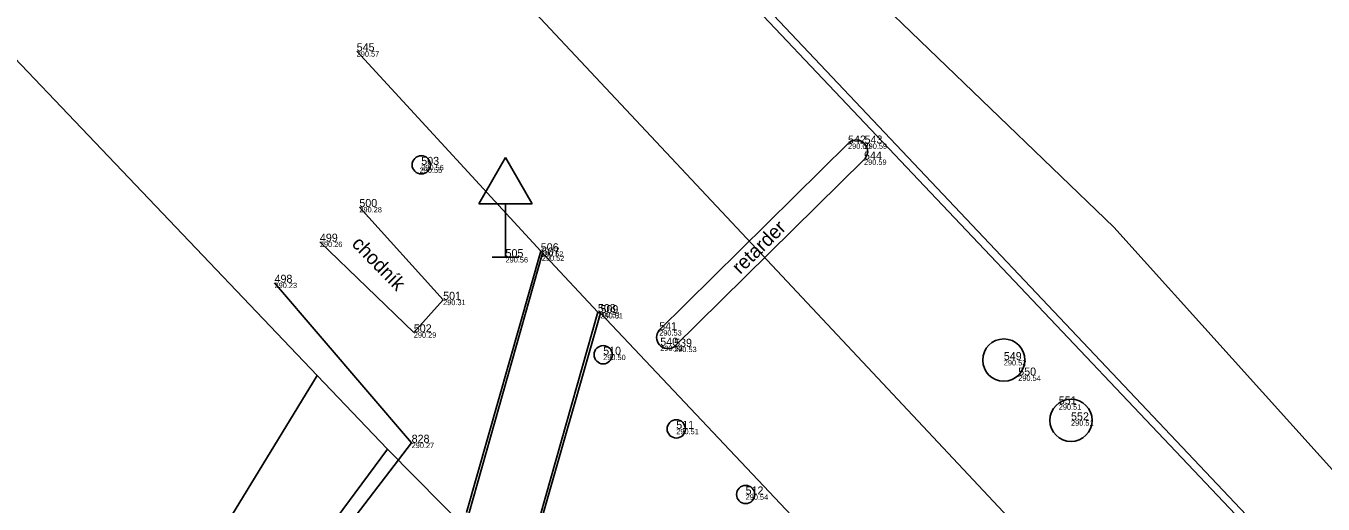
# Model space of a CAD drawing. Extents: x -805057 to -804930, y -994399 to -994240.
# Drawn here: x -805024.17 to -804999.86, y -994267.14 to -994258.18 of the extents above; entities that cross this region are included whole.
import ezdxf

# ---------------------------------------------------------------- set-up
doc = ezdxf.new("R2010")
doc.units = 0
for name, color, linetype in [('bod cislo', 7, 'Continuous'), ('bod pozice', 7, 'Continuous'), ('bod výška', 7, 'Continuous'), ('kanalizace', 7, 'Continuous'), ('Katastralni mapa', 7, 'Continuous'), ('komunikace', 7, 'Continuous'), ('plot', 7, 'Continuous'), ('popis', 7, 'Continuous'), ('sloupek', 7, 'Continuous'), ('značka', 7, 'Continuous')]:
    doc.layers.add(name, color=color, linetype=linetype)

msp = doc.modelspace()

# ---------------------------------------------------------------- linework, layer by layer
at = {"layer": 'bod pozice'}
for p, q in [((-805017.97, -994258.65), (-805017.97, -994258.65)), ((-805008.76, -994260.38), (-805008.76, -994260.38)), ((-805008.45, -994260.38), (-805008.45, -994260.38)), ((-805016.76, -994260.78), (-805016.76, -994260.78)), ((-805008.46, -994260.68), (-805008.46, -994260.68)), ((-805017.92, -994261.57), (-805017.92, -994261.57)), ((-805018.66, -994262.22), (-805018.66, -994262.22)), ((-805015.18, -994262.51), (-805015.18, -994262.51)), ((-805014.52, -994262.4), (-805014.52, -994262.4)), ((-805014.5, -994262.48), (-805014.5, -994262.48)), ((-805019.51, -994262.99), (-805019.51, -994262.99)), ((-805016.35, -994263.31), (-805016.35, -994263.31)), ((-805013.45, -994263.54), (-805013.45, -994263.54)), ((-805013.4, -994263.56), (-805013.4, -994263.56)), ((-805016.9, -994263.92), (-805016.9, -994263.92)), ((-805012.3, -994263.88), (-805012.3, -994263.88)), ((-805012.28, -994264.17), (-805012.28, -994264.17)), ((-805012.02, -994264.19), (-805012.02, -994264.19)), ((-805013.35, -994264.34), (-805013.35, -994264.34)), ((-805005.84, -994264.44), (-805005.84, -994264.44)), ((-805005.57, -994264.73), (-805005.57, -994264.73)), ((-805004.81, -994265.27), (-805004.81, -994265.27)), ((-805011.98, -994265.73), (-805011.98, -994265.73)), ((-805004.58, -994265.57), (-805004.58, -994265.57)), ((-805016.94, -994265.99), (-805016.94, -994265.99)), ((-805010.68, -994266.96), (-805010.68, -994266.96))]:
    msp.add_line(p, q, dxfattribs=at)
at = {"layer": 'kanalizace'}
for centre in [(-805005.84, -994264.44), (-805004.58, -994265.57)]:
    msp.add_circle(centre, 0.396, dxfattribs=at)
at = {"layer": 'Katastralni mapa'}
for points in [[(-805025.53, -994257.57), (-805018.71, -994264.73)], [(-805008.4, -994257.49), (-805003.78, -994261.95)], [(-805003.78, -994261.95), (-804999.34, -994266.87)], [(-805018.71, -994264.73), (-805029.78, -994282.86)], [(-805018.71, -994264.73), (-805017.39, -994266.11)], [(-805017.39, -994266.11), (-805024.09, -994275.16)], [(-805017.39, -994266.11), (-804988.46, -994295.41)]]:
    msp.add_lwpolyline(points, dxfattribs=at)
at = {"layer": 'komunikace'}
for p, q in [((-805014.33, -994253.78), (-804993.36, -994275.93)), ((-804993.27, -994275.83), (-805014.23, -994253.66)), ((-805005.75, -994267.39), (-805015.94, -994256.52)), ((-805017.97, -994258.65), (-805014.52, -994262.4)), ((-805008.76, -994260.38), (-805012.3, -994263.88)), ((-805012.02, -994264.19), (-805008.46, -994260.68)), ((-805017.92, -994261.57), (-805016.35, -994263.31)), ((-805016.9, -994263.92), (-805018.66, -994262.22)), ((-805015.91, -994267.3), (-805014.52, -994262.4)), ((-805014.487, -994262.435), (-805015.87, -994267.32)), ((-805013.45, -994263.54), (-805014.52, -994262.4)), ((-805016.35, -994263.31), (-805016.9, -994263.92)), ((-805014.79, -994268.27), (-805013.45, -994263.54)), ((-805013.45, -994263.54), (-805013.4, -994263.56)), ((-805013.4, -994263.56), (-805014.75, -994268.28)), ((-805009.04, -994268.18), (-805013.4, -994263.56))]:
    msp.add_line(p, q, dxfattribs=at)
for centre, major_axis, ratio, start_param, end_param in [((-805008.605, -994260.525), (-0.007, -0.212), 0.99948, 0.785675, 3.993875), ((-805012.138, -994264.015), (0.141, -0.157), 0.998452, 3.285695, 6.139083)]:
    msp.add_ellipse(centre, major_axis=major_axis, ratio=ratio, start_param=start_param, end_param=end_param, dxfattribs=at)
at = {"layer": 'plot'}
msp.add_lwpolyline([(-805032.38, -994286.17), (-805016.94, -994265.99), (-805019.51, -994262.99)], dxfattribs=at)
at = {"layer": 'sloupek'}
for centre in [(-805016.76, -994260.78), (-805016.76, -994260.78), (-805013.35, -994264.34), (-805013.35, -994264.34), (-805011.98, -994265.73), (-805011.98, -994265.73), (-805010.68, -994266.96), (-805010.68, -994266.96)]:
    msp.add_circle(centre, 0.171, dxfattribs=at)
at = {"layer": 'značka'}
for p, q in [((-805015.18, -994260.644), (-805015.68, -994261.51)), ((-805015.18, -994260.644), (-805014.68, -994261.51)), ((-805015.68, -994261.51), (-805014.68, -994261.51)), ((-805015.18, -994262.51), (-805015.18, -994261.51)), ((-805015.43, -994262.51), (-805014.93, -994262.51))]:
    msp.add_line(p, q, dxfattribs=at)

# ---------------------------------------------------------------- texts
at = {"layer": 'bod cislo'}
for s, p in [('545    ', (-805017.97, -994258.65)), ('542    ', (-805008.76, -994260.38)), ('543    ', (-805008.45, -994260.38)), ('503    ', (-805016.76, -994260.78)), ('544    ', (-805008.46, -994260.68)), ('500    ', (-805017.92, -994261.57)), ('499    ', (-805018.66, -994262.22)), ('506    ', (-805014.52, -994262.4)), ('507    ', (-805014.5, -994262.48)), ('505    ', (-805015.18, -994262.51)), ('498    ', (-805019.51, -994262.99)), ('501    ', (-805016.35, -994263.31)), ('508    ', (-805013.45, -994263.54)), ('509    ', (-805013.4, -994263.56)), ('502    ', (-805016.9, -994263.92)), ('541    ', (-805012.3, -994263.88)), ('540    ', (-805012.28, -994264.17)), ('510    ', (-805013.35, -994264.34)), ('539    ', (-805012.02, -994264.19)), ('549    ', (-805005.84, -994264.44)), ('550    ', (-805005.57, -994264.73)), ('551    ', (-805004.81, -994265.27)), ('552    ', (-805004.58, -994265.57)), ('511    ', (-805011.98, -994265.73)), ('828', (-805016.94, -994265.99)), ('512    ', (-805010.68, -994266.96))]:
    msp.add_text(s, height=0.15, dxfattribs=at).set_placement(p)
at = {"layer": 'bod výška'}
for s, p in [('290.57  ', (-805017.97, -994258.75)), ('290.60  ', (-805008.76, -994260.48)), ('290.59  ', (-805008.45, -994260.48)), ('290.55  ', (-805016.79, -994260.93)), ('290.56  ', (-805016.76, -994260.88)), ('290.59  ', (-805008.46, -994260.78)), ('290.28  ', (-805017.92, -994261.67)), ('290.26  ', (-805018.66, -994262.32)), ('290.56  ', (-805015.18, -994262.61)), ('290.52  ', (-805014.52, -994262.5)), ('290.52  ', (-805014.5, -994262.58)), ('290.23  ', (-805019.51, -994263.09)), ('290.31  ', (-805016.35, -994263.41)), ('290.51  ', (-805013.45, -994263.64)), ('290.51  ', (-805013.4, -994263.66)), ('290.29  ', (-805016.9, -994264.02)), ('290.53  ', (-805012.3, -994263.98)), ('290.52  ', (-805012.28, -994264.27)), ('290.53  ', (-805012.02, -994264.29)), ('290.50  ', (-805013.35, -994264.44)), ('290.52  ', (-805005.84, -994264.54)), ('290.54  ', (-805005.57, -994264.83)), ('290.51  ', (-805004.81, -994265.37)), ('290.51  ', (-805011.98, -994265.83)), ('290.51  ', (-805004.58, -994265.67)), ('290.27', (-805016.94, -994266.09)), ('290.54  ', (-805010.68, -994267.06))]:
    msp.add_text(s, height=0.1, dxfattribs=at).set_placement(p)
at = {"layer": 'popis'}
for s, rotation, p in [('retarder', 44.4615, (-805010.781, -994262.843)), ('chodník', 314.1489, (-805018.078, -994262.277))]:
    msp.add_text(s, height=0.2629, rotation=rotation, dxfattribs=at).set_placement(p)

doc.saveas('drawing.dxf')
